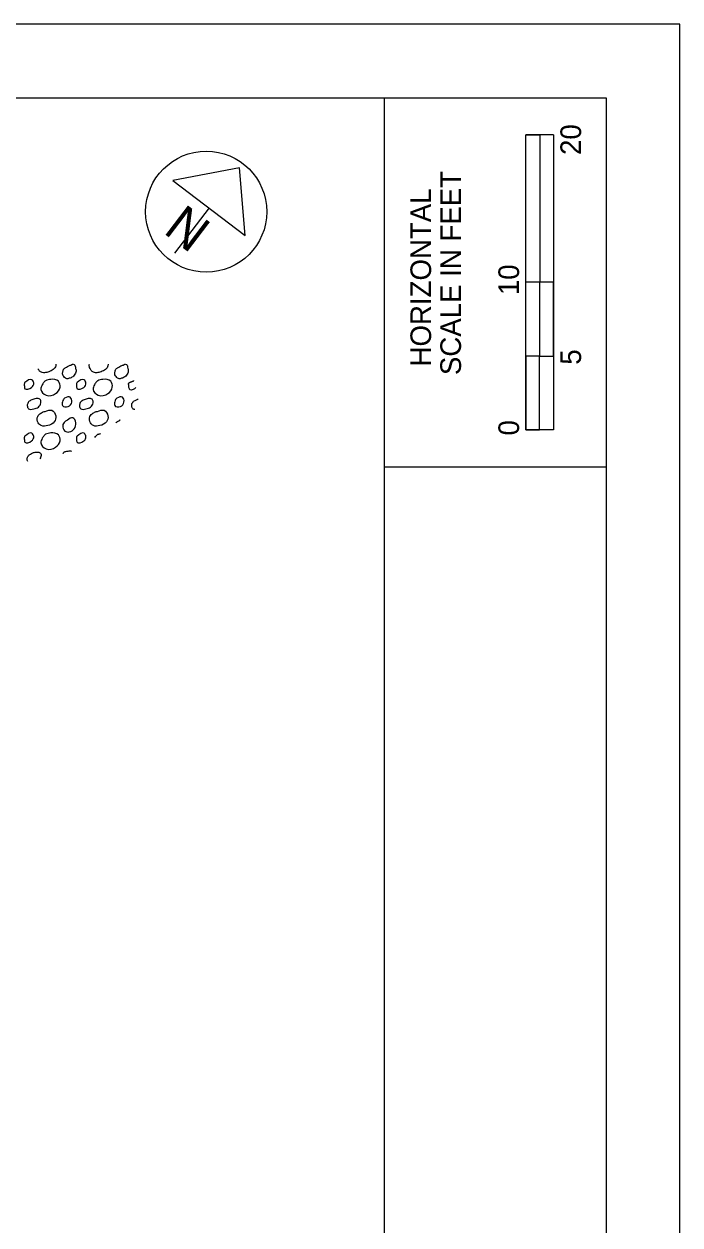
# Model space of a CAD drawing. Extents: x 1052 to 3483, y 402 to 622.
# Drawn here: x 1347.3 to 1391.7, y 540.4 to 621.8 of the extents above; entities that cross this region are included whole.
import ezdxf

# ---------------------------------------------------------------- set-up
doc = ezdxf.new("R2010")
doc.units = 0
for name, color, linetype in [('BD_X_Building', 7, 'Continuous'), ('PF_P_Grade_Line', 7, 'Continuous'), ('RW_X_CL_100_Stations', 7, 'Continuous'), ('SC_Scratch1', 7, 'Continuous'), ('SV_X_Shot_Marker', 7, 'Continuous'), ('TX_P_20', 7, 'Continuous')]:
    doc.layers.add(name, color=color, linetype=linetype)

msp = doc.modelspace()

# ---------------------------------------------------------------- linework, layer by layer
at = {"layer": 'BD_X_Building'}
for p, q in [((1361.91, 612.04), (1357.395, 611.19)), ((1362.288, 607.461), (1361.91, 612.04)), ((1357.395, 611.19), (1362.288, 607.461)), ((1359.841, 609.326), (1357.497, 606.25))]:
    msp.add_line(p, q, dxfattribs=at)
msp.add_circle((1359.645, 609.067), 4.1, dxfattribs=at)
at = {"layer": 'PF_P_Grade_Line'}
msp.add_circle((1359.645, 609.067), 4.1, dxfattribs=at)
at = {"layer": 'RW_X_CL_100_Stations'}
for p, q in [((1381.292, 594.286), (1381.292, 614.286)), ((1383.167, 614.286), (1381.292, 614.286)), ((1381.292, 604.286), (1381.292, 614.286)), ((1381.292, 614.286), (1382.225, 614.286)), ((1382.225, 614.286), (1382.234, 614.286)), ((1382.234, 614.286), (1382.234, 604.286)), ((1383.167, 614.286), (1383.167, 594.286)), ((1382.234, 604.286), (1381.292, 604.286)), ((1383.159, 604.286), (1382.225, 604.286)), ((1382.225, 604.286), (1382.225, 599.286)), ((1383.159, 599.286), (1383.159, 604.286)), ((1382.225, 599.286), (1381.292, 599.286)), ((1381.292, 599.286), (1381.292, 594.286)), ((1382.225, 594.286), (1382.225, 599.286)), ((1382.225, 599.286), (1383.159, 599.286)), ((1383.167, 594.286), (1381.292, 594.286)), ((1381.292, 594.286), (1382.225, 594.286))]:
    msp.add_line(p, q, dxfattribs=at)
at = {"layer": 'SC_Scratch1'}
msp.add_lwpolyline([(1051.725, 401.786), (1391.725, 401.786), (1391.725, 621.786), (1051.725, 621.786)], close=True, dxfattribs=at)
at = {"layer": 'SV_X_Shot_Marker'}
for p, q in [((1371.725, 406.786), (1371.725, 616.786)), ((1371.725, 591.786), (1386.725, 591.786))]:
    msp.add_line(p, q, dxfattribs=at)
msp.add_lwpolyline([(1066.725, 616.786), (1386.725, 616.786), (1386.725, 406.786), (1066.725, 406.786)], close=True, dxfattribs=at)
at = {"layer": 'TX_P_20'}
for points, degree in [([(1349.471, 598.736), (1349.47, 598.638), (1349.436, 598.536), (1349.36, 598.451), (1349.227, 598.304), (1349.078, 598.247), (1348.914, 598.199), (1348.773, 598.157), (1348.615, 598.142), (1348.474, 598.201), (1348.389, 598.237), (1348.327, 598.3), (1348.275, 598.38), (1348.266, 598.393), (1348.258, 598.407), (1348.251, 598.422)], 3), ([(1350.652, 598.736), (1350.746, 598.72), (1350.795, 598.501), (1350.818, 598.392), (1350.846, 598.261), (1350.812, 598.114), (1350.707, 597.987), (1350.607, 597.868), (1350.493, 597.811), (1350.373, 597.775), (1350.277, 597.746), (1350.156, 597.741), (1350.062, 597.834), (1349.949, 597.946), (1349.906, 598.079), (1349.929, 598.193), (1349.947, 598.284), (1349.99, 598.404), (1350.075, 598.461), (1350.136, 598.501), (1350.198, 598.54), (1350.259, 598.58)], 3), ([(1350.259, 598.58), (1350.376, 598.63), (1350.493, 598.68), (1350.611, 598.731), (1350.617, 598.733), (1350.624, 598.735), (1350.63, 598.736)], 3), ([(1353.007, 598.736), (1353.006, 598.638), (1352.972, 598.536), (1352.896, 598.451), (1352.762, 598.304), (1352.614, 598.247), (1352.45, 598.199), (1352.309, 598.157), (1352.15, 598.142), (1352.01, 598.201), (1351.924, 598.237), (1351.862, 598.3), (1351.811, 598.38), (1351.743, 598.485), (1351.712, 598.621), (1351.739, 598.736)], 3), ([(1354.188, 598.736), (1354.282, 598.72), (1354.331, 598.501), (1354.354, 598.392), (1354.382, 598.261), (1354.348, 598.114), (1354.242, 597.987), (1354.143, 597.868), (1354.029, 597.811), (1353.909, 597.775), (1353.813, 597.746), (1353.692, 597.741), (1353.598, 597.834), (1353.484, 597.946), (1353.442, 598.079), (1353.465, 598.193), (1353.483, 598.284), (1353.525, 598.404), (1353.611, 598.461), (1353.672, 598.501), (1353.734, 598.54), (1353.795, 598.58)], 3), ([(1353.795, 598.58), (1353.912, 598.63), (1354.029, 598.68), (1354.147, 598.731), (1354.153, 598.733), (1354.159, 598.735), (1354.166, 598.736)], 3), ([(1354.886, 597.154), (1354.774, 597.021), (1354.496, 596.926), (1354.438, 597.072), (1354.407, 597.151), (1354.402, 597.231), (1354.399, 597.312), (1354.397, 597.352), (1354.382, 597.397), (1354.403, 597.433), (1354.414, 597.451), (1354.426, 597.467), (1354.437, 597.485)], 3), ([(1354.437, 597.485), (1354.543, 597.528), (1354.649, 597.573), (1354.755, 597.616)], 2), ([(1354.819, 595.656), (1354.774, 595.657), (1354.73, 595.671), (1354.688, 595.708), (1354.615, 595.774), (1354.6, 595.85), (1354.602, 595.924), (1354.604, 595.99), (1354.612, 596.069), (1354.654, 596.124), (1354.679, 596.157), (1354.703, 596.189), (1354.728, 596.221)], 3), ([(1354.728, 596.221), (1354.811, 596.263), (1354.895, 596.304), (1354.978, 596.346), (1354.996, 596.355), (1355.014, 596.362), (1355.033, 596.369)], 3), ([(1353.546, 594.766), (1353.564, 594.791), (1353.586, 594.813), (1353.611, 594.83), (1353.672, 594.871), (1353.734, 594.909), (1353.795, 594.949)], 3), ([(1353.795, 594.949), (1353.806, 594.954), (1353.818, 594.959), (1353.829, 594.964)], 2), ([(1352.115, 593.765), (1352.146, 593.815), (1352.177, 593.862), (1352.219, 593.903), (1352.246, 593.929), (1352.273, 593.954), (1352.3, 593.98)], 3), ([(1352.3, 593.98), (1352.365, 593.998), (1352.431, 594.015), (1352.496, 594.032)], 2), ([(1347.571, 592.13), (1347.537, 592.182), (1347.529, 592.238), (1347.531, 592.294), (1347.532, 592.36), (1347.541, 592.438), (1347.582, 592.494), (1347.607, 592.526), (1347.632, 592.558), (1347.657, 592.59)], 3), ([(1347.657, 592.59), (1347.74, 592.632), (1347.823, 592.674), (1347.907, 592.715), (1347.998, 592.761), (1348.108, 592.77), (1348.207, 592.773), (1348.281, 592.775), (1348.352, 592.758), (1348.418, 592.692), (1348.479, 592.632), (1348.47, 592.552), (1348.452, 592.489), (1348.436, 592.43), (1348.417, 592.372), (1348.385, 592.316)], 3), ([(1349.955, 592.675), (1349.961, 592.686), (1349.967, 592.697), (1349.975, 592.706), (1350.001, 592.74), (1350.028, 592.774), (1350.055, 592.807)], 3), ([(1350.055, 592.807), (1350.182, 592.825), (1350.309, 592.846), (1350.437, 592.863), (1350.475, 592.868), (1350.504, 592.843), (1350.523, 592.804)], 3)]:
    msp.add_open_spline(points, degree=degree, dxfattribs=at)
for points in [[(1347.365, 597.485), (1347.84, 597.677), (1347.966, 597.459), (1347.817, 597.156), (1347.367, 597.072), (1347.327, 597.312), (1347.332, 597.433), (1347.365, 597.485)], [(1348.764, 597.611), (1349.12, 597.704), (1349.641, 597.572), (1349.748, 597.17), (1349.452, 596.735), (1348.804, 596.624), (1348.45, 597.022), (1348.545, 597.341), (1348.683, 597.533), (1348.764, 597.611)], [(1350.901, 597.485), (1351.376, 597.677), (1351.502, 597.459), (1351.352, 597.156), (1350.902, 597.072), (1350.863, 597.312), (1350.867, 597.433), (1350.901, 597.485)], [(1352.3, 597.611), (1352.656, 597.704), (1353.177, 597.572), (1353.284, 597.17), (1352.988, 596.735), (1352.34, 596.624), (1351.986, 597.022), (1352.081, 597.341), (1352.219, 597.533), (1352.3, 597.611)], [(1347.657, 596.221), (1347.907, 596.346), (1348.207, 596.403), (1348.418, 596.323), (1348.452, 596.119), (1348.282, 595.823), (1347.968, 595.703), (1347.617, 595.708), (1347.531, 595.924), (1347.582, 596.124), (1347.657, 596.221)], [(1350.055, 596.438), (1350.437, 596.493), (1350.541, 596.165), (1350.301, 595.871), (1349.914, 595.928), (1349.917, 596.173), (1349.975, 596.337), (1350.055, 596.438)], [(1351.192, 596.221), (1351.442, 596.346), (1351.743, 596.403), (1351.954, 596.323), (1351.988, 596.119), (1351.817, 595.823), (1351.504, 595.703), (1351.152, 595.708), (1351.067, 595.924), (1351.118, 596.124), (1351.192, 596.221)], [(1353.591, 596.438), (1353.972, 596.493), (1354.077, 596.165), (1353.837, 595.871), (1353.45, 595.928), (1353.452, 596.173), (1353.511, 596.337), (1353.591, 596.438)], [(1348.743, 595.532), (1349.197, 595.608), (1349.457, 595.228), (1349.36, 594.821), (1348.914, 594.568), (1348.474, 594.571), (1348.275, 594.749), (1348.238, 595.194), (1348.443, 595.408), (1348.669, 595.516), (1348.752, 595.533)], [(1350.259, 594.949), (1350.611, 595.1), (1350.818, 594.762), (1350.707, 594.357), (1350.373, 594.144), (1350.062, 594.203), (1349.929, 594.563), (1350.075, 594.83), (1350.259, 594.949)], [(1352.279, 595.532), (1352.733, 595.608), (1352.992, 595.228), (1352.896, 594.821), (1352.45, 594.568), (1352.01, 594.571), (1351.811, 594.749), (1351.774, 595.194), (1351.979, 595.408), (1352.205, 595.516), (1352.287, 595.533)], [(1347.365, 593.854), (1347.84, 594.047), (1347.966, 593.828), (1347.817, 593.526), (1347.367, 593.442), (1347.327, 593.682), (1347.332, 593.803), (1347.365, 593.854)], [(1348.764, 593.98), (1349.12, 594.073), (1349.641, 593.942), (1349.748, 593.539), (1349.452, 593.104), (1348.804, 592.993), (1348.45, 593.392), (1348.545, 593.71), (1348.683, 593.903), (1348.764, 593.98)], [(1350.901, 593.854), (1351.376, 594.047), (1351.502, 593.828), (1351.352, 593.526), (1350.902, 593.442), (1350.863, 593.682), (1350.867, 593.803), (1350.901, 593.854)]]:
    msp.add_spline(points, degree=3, dxfattribs=at)

# ---------------------------------------------------------------- texts
at = {"layer": 'BD_X_Building'}
msp.add_text('N', height=2.5, rotation=322.69097, dxfattribs=at).set_placement((1356.675, 607.667))
at = {"layer": 'RW_X_CL_100_Stations'}
for s, p in [('20', (1385.029, 612.911)), ('SCALE IN FEET', (1376.9, 597.992)), ('HORIZONTAL', (1374.875, 598.578)), ('10', (1380.83, 603.411)), ('5', (1385.029, 598.698)), ('0', (1380.83, 593.899))]:
    msp.add_text(s, height=1.4, rotation=90, dxfattribs=at).set_placement(p)

doc.saveas('drawing.dxf')
